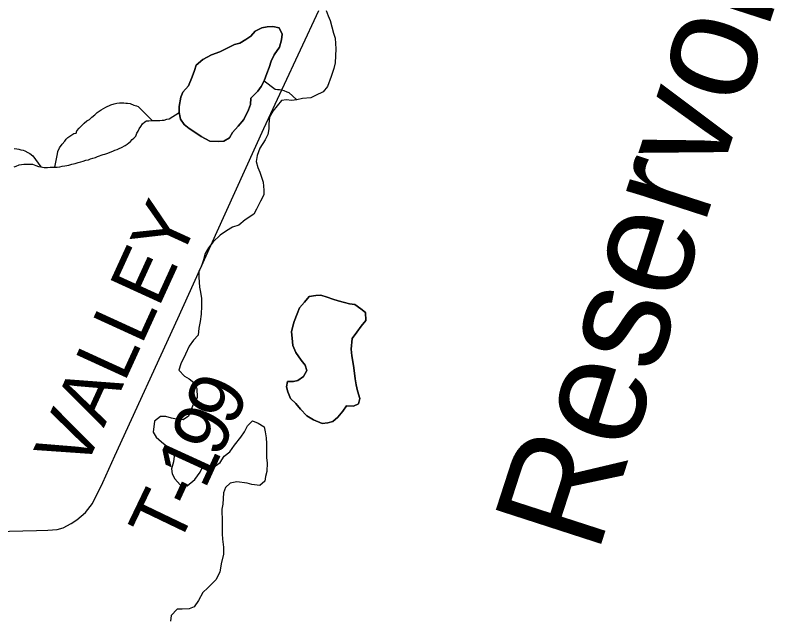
# Model space of a CAD drawing. Extents: x 10.6 to 44.6, y -2.6 to 23.4.
# Drawn here: x 14.299 to 15.089, y 18.108 to 18.724 of the extents above; entities that cross this region are included whole.
import ezdxf

# ---------------------------------------------------------------- set-up
doc = ezdxf.new("R2010")
doc.units = 0
for name, color, linetype in [('GM_X_Major_Lake', 7, 'Continuous'), ('GM_X_Major_Lake_Text', 7, 'Continuous'), ('GM_X_Major_River', 7, 'Continuous'), ('GM_X_Minor_Lake', 7, 'Continuous'), ('GM_X_Minor_River', 7, 'Continuous'), ('GM_X_Township_Road', 7, 'Continuous'), ('GM_X_Township_Road_Text', 7, 'Continuous')]:
    doc.layers.add(name, color=color, linetype=linetype)

msp = doc.modelspace()

# ---------------------------------------------------------------- linework, layer by layer
at = {"layer": 'GM_X_Major_Lake'}
for points in [[(14.61775, 18.72883), (14.62002, 18.72352), (14.62192, 18.71858), (14.62533, 18.70567), (14.62723, 18.70035), (14.62798, 18.68934), (14.62722, 18.67528), (14.6257, 18.6692), (14.62304, 18.66122), (14.61925, 18.65096), (14.61469, 18.64525), (14.6071, 18.64145), (14.60217, 18.63916), (14.59344, 18.63839), (14.58775, 18.63724), (14.58244, 18.63648), (14.57713, 18.63723), (14.5722, 18.63647), (14.56309, 18.62544), (14.55967, 18.61974), (14.55891, 18.61214), (14.55891, 18.6072), (14.55815, 18.6015), (14.55511, 18.59618), (14.5498, 18.58744), (14.54714, 18.57984), (14.546, 18.57376), (14.5479, 18.56768), (14.54979, 18.56274), (14.5532, 18.55249)], [(14.5532, 18.55249), (14.55396, 18.54451), (14.55396, 18.53957), (14.55055, 18.53311), (14.54637, 18.52475), (14.54371, 18.51981), (14.5346, 18.5141), (14.52815, 18.50839), (14.5217, 18.50649), (14.51563, 18.50268), (14.50918, 18.49811), (14.50197, 18.49127), (14.49703, 18.48519), (14.49362, 18.47948), (14.4921, 18.47302), (14.48982, 18.46656), (14.48716, 18.46086), (14.48716, 18.45516), (14.48792, 18.44491), (14.48906, 18.43959), (14.48981, 18.43313), (14.48981, 18.42515), (14.48943, 18.41718), (14.48867, 18.40958), (14.48715, 18.40274), (14.48639, 18.39552), (14.48184, 18.39058), (14.47728, 18.38411), (14.47349, 18.37613), (14.46855, 18.36625), (14.46665, 18.35979), (14.47234, 18.35334), (14.47727, 18.35068), (14.4822, 18.34689), (14.48524, 18.34081), (14.48561, 18.3317), (14.4822, 18.326), (14.47992, 18.32106), (14.4765, 18.31231), (14.47119, 18.30851), (14.46588, 18.30888), (14.45905, 18.31039), (14.45336, 18.31191), (14.44767, 18.3119), (14.4416, 18.30734), (14.44046, 18.29594), (14.44349, 18.291), (14.4488, 18.28607), (14.45449, 18.28152), (14.45942, 18.2762), (14.4617, 18.27127), (14.46132, 18.26557), (14.45904, 18.25835), (14.4598, 18.25303), (14.46245, 18.2481), (14.46814, 18.24202), (14.47535, 18.24089), (14.48294, 18.24736), (14.48863, 18.25497), (14.49243, 18.26295), (14.49774, 18.26219), (14.50419, 18.26144), (14.50912, 18.26487), (14.5133, 18.27133), (14.51899, 18.27589), (14.52392, 18.28274), (14.53038, 18.29072), (14.53417, 18.29642), (14.53721, 18.30251), (14.54214, 18.30745), (14.54821, 18.30518), (14.55428, 18.30139), (14.55542, 18.29645), (14.55618, 18.28999), (14.55655, 18.2843), (14.55655, 18.26948), (14.55731, 18.26454), (14.55693, 18.25543), (14.55579, 18.25049), (14.55503, 18.24554), (14.54971, 18.24136), (14.54175, 18.24211), (14.53681, 18.24363), (14.52619, 18.24513), (14.51936, 18.2436), (14.51443, 18.23904), (14.51253, 18.23372), (14.51215, 18.22802), (14.51177, 18.22194), (14.51063, 18.217), (14.511, 18.20409), (14.511, 18.19155), (14.51138, 18.18623), (14.51252, 18.17788), (14.51251, 18.17066), (14.51024, 18.16078), (14.50872, 18.15242), (14.50454, 18.14444), (14.49657, 18.13607), (14.49126, 18.13151), (14.4867, 18.12314)], [(14.5782, 18.34814), (14.57706, 18.34244), (14.57857, 18.3375), (14.58123, 18.33067), (14.58692, 18.32536), (14.59147, 18.31966), (14.59791, 18.31283), (14.60474, 18.30866), (14.61385, 18.30488), (14.61954, 18.30564), (14.62485, 18.30679), (14.62979, 18.31135), (14.6351, 18.31744), (14.6389, 18.32314), (14.6461, 18.32277), (14.65104, 18.32505), (14.65256, 18.33037), (14.6499, 18.33835), (14.64877, 18.34442), (14.64763, 18.35088), (14.64687, 18.35658), (14.64611, 18.36456), (14.64422, 18.37443), (14.64346, 18.38127), (14.6446, 18.39228), (14.64954, 18.39875), (14.65371, 18.40483), (14.65865, 18.41054), (14.65827, 18.41889), (14.65334, 18.42269), (14.64727, 18.42686), (14.64196, 18.42761), (14.63665, 18.42913), (14.6302, 18.43064), (14.62488, 18.43253), (14.61881, 18.43442), (14.61237, 18.43669), (14.60743, 18.43631), (14.6006, 18.43516), (14.59567, 18.42946), (14.59036, 18.42375), (14.58808, 18.41729), (14.58504, 18.40969), (14.58352, 18.40475), (14.58238, 18.39905), (14.58314, 18.39259), (14.58352, 18.385), (14.58693, 18.37778), (14.59224, 18.36981), (14.59641, 18.36488), (14.59793, 18.35918), (14.59451, 18.3531), (14.58882, 18.34891), (14.58427, 18.34815)], [(14.58427, 18.34815), (14.5782, 18.34814)], [(14.4867, 18.12314), (14.48253, 18.11668), (14.47721, 18.11477), (14.47001, 18.11439), (14.46507, 18.11438), (14.45862, 18.10792), (14.45824, 18.10184)]]:
    msp.add_lwpolyline(points, dxfattribs=at)
at = {"layer": 'GM_X_Major_River'}
for points in [[(14.61775, 18.72883), (14.62002, 18.72352), (14.62192, 18.71858), (14.62533, 18.70567), (14.62723, 18.70035), (14.62798, 18.68934), (14.62722, 18.67528), (14.6257, 18.6692), (14.62304, 18.66122), (14.61925, 18.65096), (14.61469, 18.64525), (14.6071, 18.64145), (14.60217, 18.63916), (14.59344, 18.63839), (14.58775, 18.63724), (14.58244, 18.63648), (14.57713, 18.63723), (14.5722, 18.63647), (14.56309, 18.62544), (14.55967, 18.61974), (14.55891, 18.61214), (14.55891, 18.6072), (14.55815, 18.6015), (14.55511, 18.59618), (14.5498, 18.58744), (14.54714, 18.57984), (14.546, 18.57376), (14.5479, 18.56768), (14.54979, 18.56274), (14.5532, 18.55249)], [(14.5532, 18.55249), (14.55396, 18.54451), (14.55396, 18.53957), (14.55055, 18.53311), (14.54637, 18.52475), (14.54371, 18.51981), (14.5346, 18.5141), (14.52815, 18.50839), (14.5217, 18.50649), (14.51563, 18.50268), (14.50918, 18.49811), (14.50197, 18.49127), (14.49703, 18.48519), (14.49362, 18.47948), (14.4921, 18.47302), (14.48982, 18.46656), (14.48716, 18.46086), (14.48716, 18.45516), (14.48792, 18.44491), (14.48906, 18.43959), (14.48981, 18.43313), (14.48981, 18.42515), (14.48943, 18.41718), (14.48867, 18.40958), (14.48715, 18.40274), (14.48639, 18.39552), (14.48184, 18.39058), (14.47728, 18.38411), (14.47349, 18.37613), (14.46855, 18.36625), (14.46665, 18.35979), (14.47234, 18.35334), (14.47727, 18.35068), (14.4822, 18.34689), (14.48524, 18.34081), (14.48561, 18.3317), (14.4822, 18.326), (14.47992, 18.32106), (14.4765, 18.31231), (14.47119, 18.30851), (14.46588, 18.30888), (14.45905, 18.31039), (14.45336, 18.31191), (14.44767, 18.3119), (14.4416, 18.30734), (14.44046, 18.29594), (14.44349, 18.291), (14.4488, 18.28607), (14.45449, 18.28152), (14.45942, 18.2762), (14.4617, 18.27127), (14.46132, 18.26557), (14.45904, 18.25835), (14.4598, 18.25303), (14.46245, 18.2481), (14.46814, 18.24202), (14.47535, 18.24089), (14.48294, 18.24736), (14.48863, 18.25497), (14.49243, 18.26295), (14.49774, 18.26219), (14.50419, 18.26144), (14.50912, 18.26487), (14.5133, 18.27133), (14.51899, 18.27589), (14.52392, 18.28274), (14.53038, 18.29072), (14.53417, 18.29642), (14.53721, 18.30251), (14.54214, 18.30745), (14.54821, 18.30518), (14.55428, 18.30139), (14.55542, 18.29645), (14.55618, 18.28999), (14.55655, 18.2843), (14.55655, 18.26948), (14.55731, 18.26454), (14.55693, 18.25543), (14.55579, 18.25049), (14.55503, 18.24554), (14.54971, 18.24136), (14.54175, 18.24211), (14.53681, 18.24363), (14.52619, 18.24513), (14.51936, 18.2436), (14.51443, 18.23904), (14.51253, 18.23372), (14.51215, 18.22802), (14.51177, 18.22194), (14.51063, 18.217), (14.511, 18.20409), (14.511, 18.19155), (14.51138, 18.18623), (14.51252, 18.17788), (14.51251, 18.17066), (14.51024, 18.16078), (14.50872, 18.15242), (14.50454, 18.14444), (14.49657, 18.13607), (14.49126, 18.13151), (14.4867, 18.12314)], [(14.58427, 18.34815), (14.58882, 18.34891), (14.59451, 18.3531), (14.59793, 18.35918), (14.59641, 18.36488), (14.59224, 18.36981), (14.58693, 18.37778), (14.58352, 18.385), (14.58314, 18.39259), (14.58238, 18.39905), (14.58352, 18.40475), (14.58504, 18.40969), (14.58808, 18.41729), (14.59036, 18.42375), (14.59567, 18.42946), (14.6006, 18.43516), (14.60743, 18.43631), (14.61237, 18.43669), (14.61881, 18.43442), (14.62488, 18.43253), (14.6302, 18.43064), (14.63665, 18.42913), (14.64196, 18.42761), (14.64727, 18.42686), (14.65334, 18.42269), (14.65827, 18.41889), (14.65865, 18.41054), (14.65371, 18.40483), (14.64954, 18.39875), (14.6446, 18.39228), (14.64346, 18.38127), (14.64422, 18.37443), (14.64611, 18.36456), (14.64687, 18.35658), (14.64763, 18.35088), (14.64877, 18.34442), (14.6499, 18.33835), (14.65256, 18.33037), (14.65104, 18.32505), (14.6461, 18.32277), (14.6389, 18.32314), (14.6351, 18.31744), (14.62979, 18.31135), (14.62485, 18.30679), (14.61954, 18.30564), (14.61385, 18.30488), (14.60474, 18.30866), (14.59791, 18.31283), (14.59147, 18.31966), (14.58692, 18.32536), (14.58123, 18.33067), (14.57857, 18.3375), (14.57706, 18.34244), (14.5782, 18.34814)], [(14.5782, 18.34814), (14.58427, 18.34815)], [(14.4867, 18.12314), (14.48253, 18.11668), (14.47721, 18.11477), (14.47001, 18.11439), (14.46507, 18.11438), (14.45862, 18.10792), (14.45824, 18.10184)]]:
    msp.add_lwpolyline(points, dxfattribs=at)
at = {"layer": 'GM_X_Minor_Lake'}
for points in [[(14.54791, 18.64594), (14.54071, 18.63871), (14.54032, 18.63225), (14.53805, 18.62693), (14.53349, 18.61705), (14.52742, 18.6102), (14.52173, 18.60374), (14.51869, 18.59804), (14.513, 18.59461), (14.50693, 18.59422), (14.49858, 18.59459), (14.48948, 18.59952), (14.48416, 18.60331), (14.47734, 18.60787), (14.47202, 18.61166), (14.46823, 18.61735), (14.4671, 18.62419), (14.4671, 18.63027), (14.46862, 18.63977), (14.4709, 18.64509), (14.47659, 18.65155), (14.48038, 18.66067), (14.48266, 18.66713), (14.48456, 18.67283), (14.49139, 18.67854), (14.50012, 18.68349), (14.50885, 18.68654), (14.51416, 18.6892), (14.52365, 18.69377), (14.52934, 18.6953), (14.53541, 18.6991), (14.54072, 18.70253), (14.5449, 18.70747), (14.55173, 18.7109), (14.55742, 18.71205), (14.56311, 18.71243), (14.56956, 18.71092), (14.57259, 18.70447), (14.57221, 18.69877), (14.56993, 18.69117), (14.56462, 18.68318), (14.56158, 18.67672), (14.55931, 18.67026), (14.55703, 18.66418), (14.55437, 18.65658), (14.55133, 18.65088), (14.54791, 18.64594)], [(14.54791, 18.64594), (14.55133, 18.65088), (14.55437, 18.65658), (14.55703, 18.66418), (14.55931, 18.67026), (14.56158, 18.67672), (14.56462, 18.68318), (14.56993, 18.69117), (14.57221, 18.69877), (14.57259, 18.70447), (14.56956, 18.71092), (14.56311, 18.71243), (14.55742, 18.71205), (14.55173, 18.7109), (14.5449, 18.70747), (14.54072, 18.70253), (14.53541, 18.6991), (14.52934, 18.6953), (14.52365, 18.69377), (14.51416, 18.6892), (14.50885, 18.68654), (14.50012, 18.68349), (14.49139, 18.67854), (14.48456, 18.67283)], [(14.48456, 18.67283), (14.48266, 18.66713), (14.48038, 18.66067), (14.47659, 18.65155), (14.4709, 18.64509), (14.46862, 18.63977), (14.4671, 18.63027), (14.4671, 18.62419), (14.46823, 18.61735), (14.47202, 18.61166), (14.47734, 18.60787), (14.48416, 18.60331), (14.48948, 18.59952), (14.49858, 18.59459), (14.50693, 18.59422), (14.513, 18.59461), (14.51869, 18.59804), (14.52173, 18.60374), (14.52742, 18.6102), (14.53349, 18.61705), (14.53805, 18.62693), (14.54032, 18.63225), (14.54071, 18.63871), (14.54791, 18.64594)]]:
    msp.add_lwpolyline(points, dxfattribs=at)
at = {"layer": 'GM_X_Minor_River'}
for points in [[(14.55437, 18.65658), (14.56554, 18.64817), (14.56783, 18.64784), (14.57011, 18.64789), (14.57202, 18.64756), (14.57432, 18.64684), (14.57739, 18.64539), (14.57969, 18.64468), (14.58775, 18.63724)], [(14.33939, 18.56801), (14.34214, 18.58175), (14.34247, 18.58403), (14.34429, 18.58788), (14.34687, 18.59173), (14.34947, 18.59483), (14.35095, 18.59676), (14.35282, 18.59832), (14.35581, 18.60067), (14.35881, 18.60263), (14.36109, 18.60306), (14.3618, 18.60536), (14.3644, 18.60807), (14.36701, 18.61079), (14.36962, 18.61313), (14.37223, 18.61547), (14.37486, 18.61704), (14.37747, 18.61938), (14.38047, 18.62173), (14.3827, 18.62405), (14.38683, 18.6268), (14.39171, 18.62957), (14.39699, 18.63197), (14.40038, 18.63318), (14.40304, 18.63362), (14.40569, 18.63406), (14.40797, 18.63411), (14.41026, 18.63415), (14.41216, 18.63381), (14.41406, 18.63386), (14.41674, 18.63353), (14.42058, 18.63172), (14.42326, 18.63102), (14.42479, 18.63029), (14.43917, 18.61578)], [(14.44716, 18.61595), (14.44943, 18.61638), (14.45171, 18.61643), (14.45436, 18.61725), (14.45663, 18.61768), (14.4671, 18.62419)], [(14.29754, 18.56824), (14.2998, 18.56905), (14.30282, 18.57025), (14.30509, 18.57068), (14.30737, 18.57111), (14.31155, 18.5712), (14.31421, 18.57126), (14.3165, 18.57093), (14.31995, 18.56986), (14.32263, 18.56878), (14.32492, 18.56845), (14.32836, 18.56777), (14.33178, 18.56784), (14.33444, 18.5679), (14.33673, 18.56795), (14.33939, 18.56801), (14.34167, 18.56806), (14.34432, 18.56849), (14.34697, 18.56893), (14.34963, 18.56937), (14.3538, 18.57022), (14.35682, 18.57105), (14.36023, 18.57188), (14.36325, 18.57271), (14.3659, 18.57352), (14.36854, 18.57434), (14.37119, 18.57516), (14.37384, 18.5756), (14.37611, 18.57641), (14.37837, 18.57721), (14.38102, 18.57803), (14.38328, 18.57884), (14.38895, 18.58087), (14.39084, 18.58129), (14.39386, 18.58249), (14.39612, 18.5833), (14.39876, 18.5845), (14.40102, 18.58531), (14.40329, 18.58612), (14.40555, 18.58731), (14.40781, 18.58812), (14.41157, 18.5901), (14.41344, 18.59166), (14.41532, 18.59284), (14.41719, 18.5944), (14.41867, 18.59633), (14.42054, 18.59789), (14.4224, 18.59983), (14.42347, 18.6029), (14.42495, 18.60483), (14.42604, 18.60752), (14.42751, 18.60983), (14.42935, 18.61253), (14.4316, 18.61448), (14.43347, 18.61566), (14.43575, 18.61571), (14.43917, 18.61578), (14.44374, 18.61588), (14.44716, 18.61595)], [(14.29751, 18.58724), (14.30018, 18.58691), (14.30247, 18.58659), (14.30439, 18.58587), (14.30668, 18.58554), (14.3086, 18.58482), (14.31168, 18.58299), (14.3136, 18.58189), (14.3167, 18.57967), (14.32492, 18.56845)]]:
    msp.add_lwpolyline(points, dxfattribs=at)
at = {"layer": 'GM_X_Township_Road'}
for points in [[(14.35603, 18.20205), (14.36194, 18.20583), (14.37093, 18.2134), (14.37802, 18.22285), (14.38866, 18.24437), (14.40095, 18.2718), (14.4655, 18.41272), (14.50617, 18.50186), (14.55393, 18.60755), (14.61044, 18.72884)], [(13.9546, 18.19027), (13.99897, 18.19125), (14.09169, 18.19212), (14.16567, 18.19297), (14.23237, 18.19377), (14.2783, 18.19411), (14.32056, 18.19519), (14.33223, 18.19531), (14.34184, 18.1959), (14.34799, 18.19779), (14.35603, 18.20205)]]:
    msp.add_lwpolyline(points, dxfattribs=at)

# ---------------------------------------------------------------- texts
at = {"layer": 'GM_X_Major_Lake_Text'}
msp.add_text('Reservoir', height=0.11372, rotation=72.06558, dxfattribs=at).set_placement((14.89641, 18.16936))
at = {"layer": 'GM_X_Township_Road_Text'}
for s, height, rotation, p in [('VALLEY', 0.056818, 65.42844, (14.36851, 18.25385)), ('9', 0.05682, 65.53256, (14.52242, 18.29999)), ('9', 0.05682, 65.50692, (14.5079, 18.26812)), ('1', 0.05682, 65.41175, (14.49329, 18.2362)), ('-', 0.05682, 65.21072, (14.48342, 18.21482)), ('T', 0.05682, 64.37413, (14.46465, 18.17568))]:
    msp.add_text(s, height=height, rotation=rotation, dxfattribs=at).set_placement(p)

doc.saveas('drawing.dxf')
